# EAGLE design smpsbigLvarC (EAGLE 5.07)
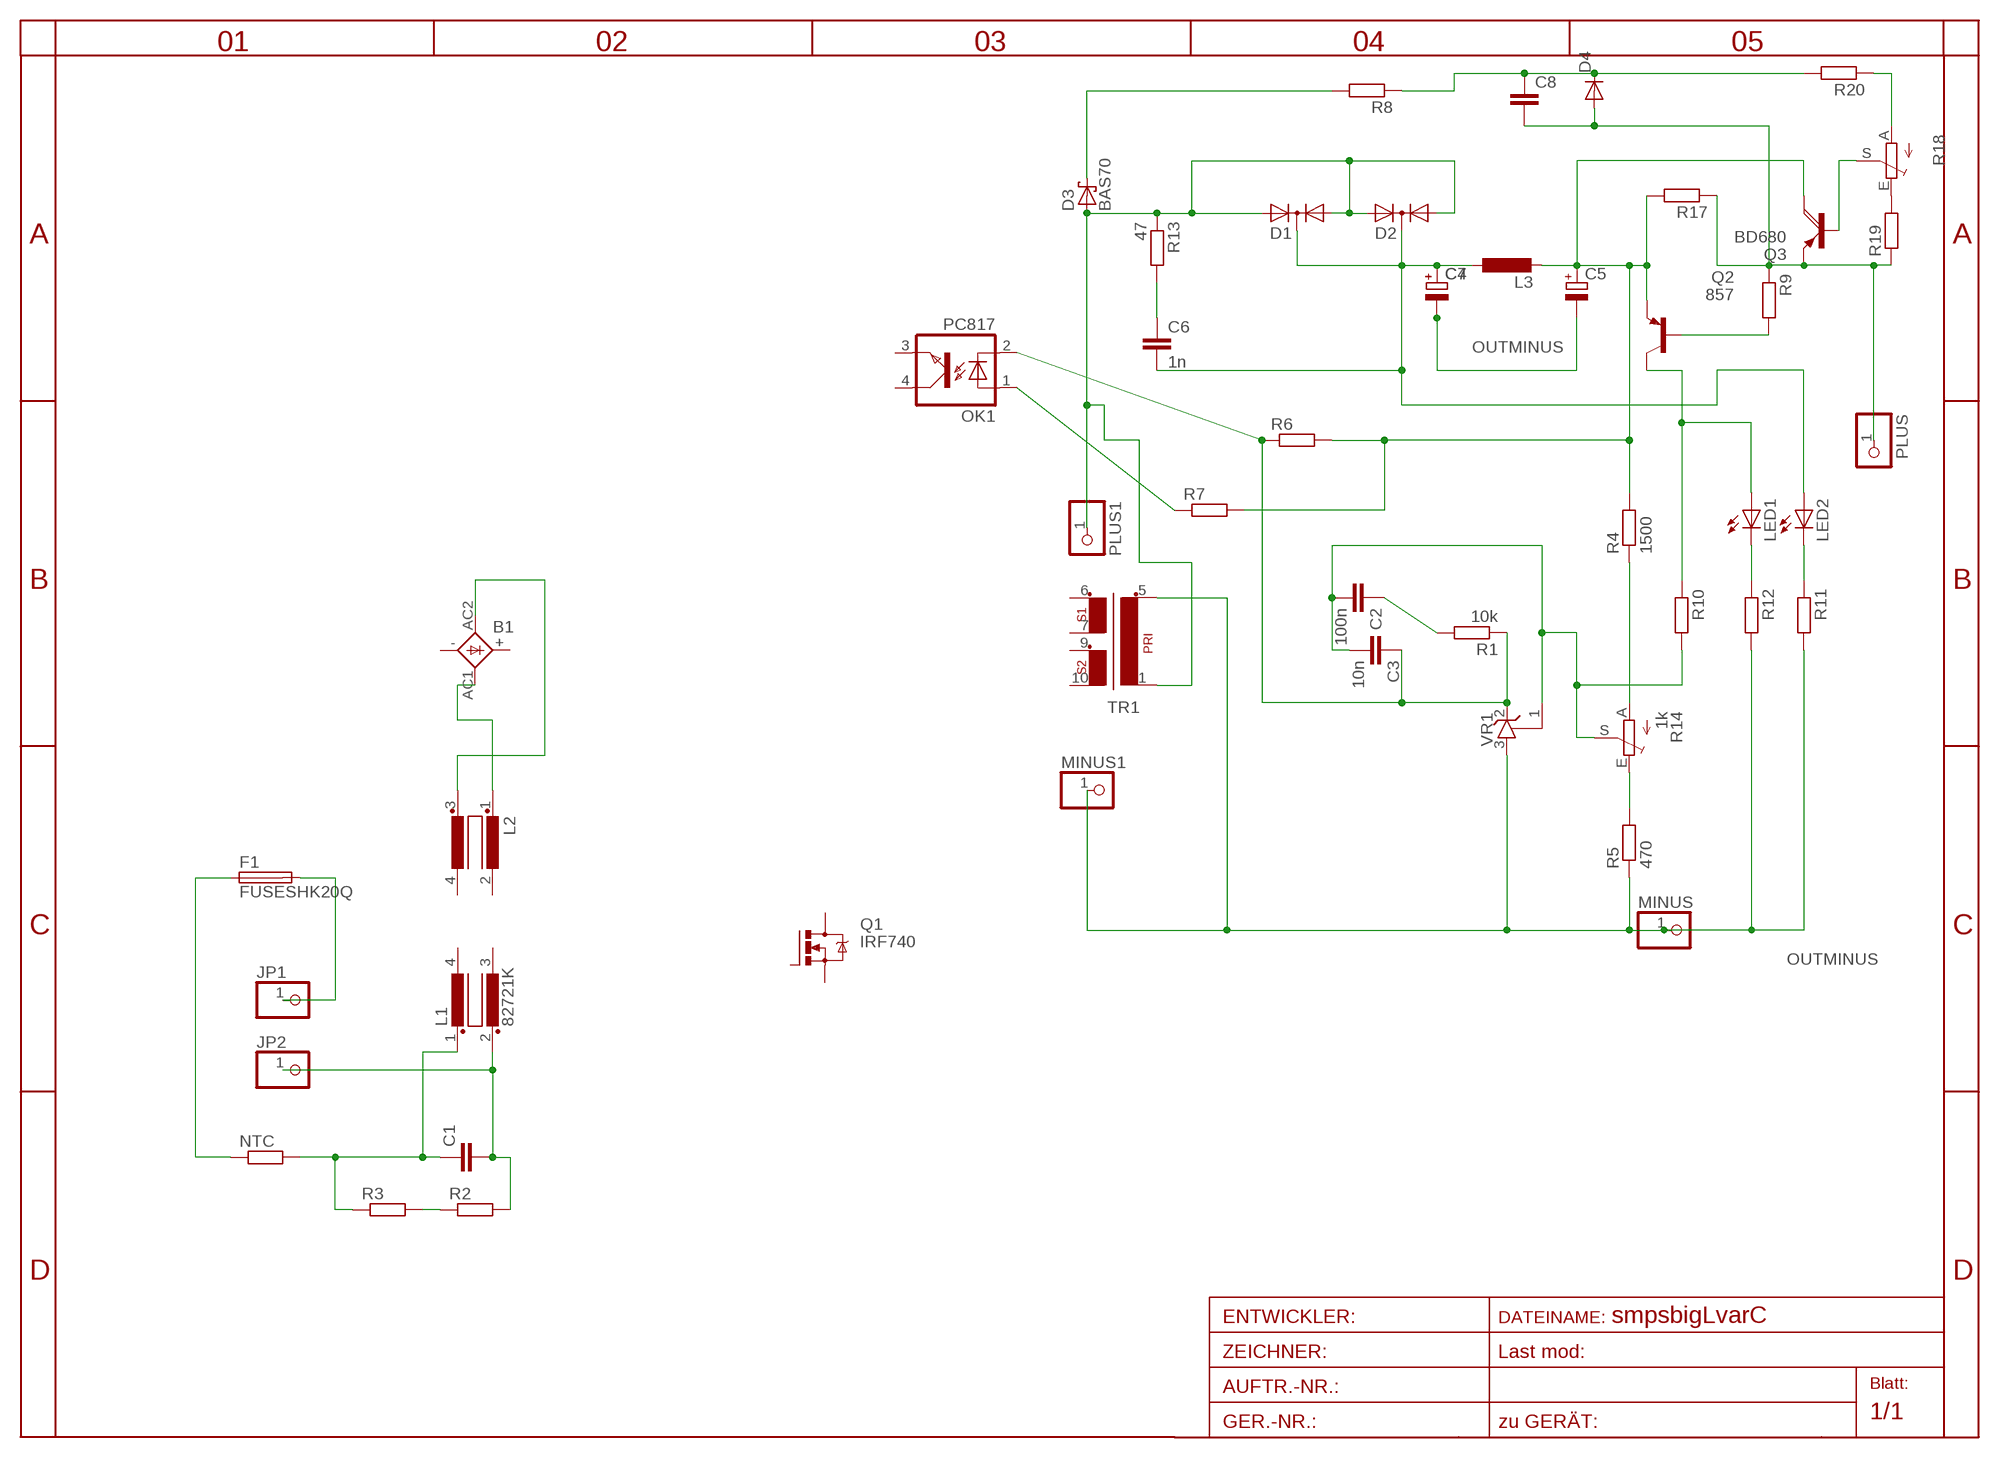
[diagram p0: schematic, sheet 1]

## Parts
B1  KBL  [KBL]
C1  C-EU150-084X183  [C150-084X183]
C2  100n  C-EUC0805  [C0805]
C3  10n  C-EUC0805  [C0805]
C4  CPOL-EUE5-8.5  [E5-8,5]
C5  CPOL-EUE5-8.5  [E5-8,5]
C6  1n  C-EUC1206  [C1206]
C7  CPOL-EUE3.5-8  [E3,5-8]
C8  C-EUC1206  [C1206]
D1  DIODE-2AC|CAIW220V  [IW220ABS]
D2  DIODE-2AC|CAIW220V  [IW220ABS]
D3  BAS70  [SOT23]
D4  DIODE-MINIMELF  [MINIMELF]
F1  FUSESHK20Q  [SHK20Q]
JP1  PINHD-1X12MM2  [1X2MM2]
JP2  PINHD-1X12MM2  [1X2MM2]
L1  82721K  [82721K]
L2  R1405VB1  [B1]
L3  L-EUOPEN6  [OPEN6_3]
LED1  LEDCHIPLED_1206  [CHIPLED_1206]
LED2  LEDCHIPLED_1206  [CHIPLED_1206]
MINUS  PINHD-1X12MM2  [1X2MM2]
MINUS1  PINHD-1X11X0.4  [1X01]
NTC  R-EU_0204/7  [0204/7]
OK1  PC817  [DIL04]
PLUS  PINHD-1X12MM2  [1X2MM2]
PLUS1  PINHD-1X11X0.4  [1X01]
Q1  IRF740  [TO220BV]
Q2  857  BC857ASMD  [SOT23-BEC]
Q3  BD680  [TO126AV]
R1  10k  R-EU_R0805  [R0805]
R2  R-EU_R1206  [R1206]
R3  R-EU_R1206  [R1206]
R4  1500  R-EU_R0805  [R0805]
R5  470  R-EU_R0805  [R0805]
R6  R-EU_R0805  [R0805]
R7  R-EU_R0805  [R0805]
R8  R-EU_R0805  [R0805]
R9  R-EU_R0805  [R0805]
R10  R-EU_R0805  [R0805]
R11  R-EU_R0805  [R0805]
R12  R-EU_R0805  [R0805]
R13  47  R-EU_R1206  [R1206]
R14  1k  TRIM_EU-S64W  [S64W]
R17  R-EU_R1206  [R1206]
R18  TRIM_EU-RAND160  [RANDL]
R19  R-EU_R0805  [R0805]
R20  R-EU_R0805  [R0805]
TR1  EE20-2  [EE30GREEN]
VR1  TL431CLPSOT23  [SOT23]

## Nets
A: R4.1 R14.A
C1: LED1.A Q2.C R10.1
CPLUS: C4.+ C6.2 C7.+ D1.C D2.C L3.1 LED2.A
E: R5.2 R14.E
N$1: C1.2 JP2.1 L1.2 R2.2
N$2: C1.1 L1.1 NTC.2 R3.1
N$3: F1.2A JP1.1
N$4: D3.3(C) R8.2
N$5: C8.1 D4.C R8.1 R20.2
N$6: R2.1 R3.2
N$7: B1.AC2(AC1) L2.3
N$8: B1.AC1(AC2) L2.1
N$9: F1.1A NTC.1
N$10: R18.E R19.2
N$11: C3.1 OK1.2(C) R1.1 R6.1 VR1.2(C)
N$12: OK1.1(A) R7.1
N$13: C2.1 R1.2
N$14: R18.A R20.1
N$15: Q3.B R18.S
N$16: Q2.B R9.2
N$21: LED1.C R12.1
N$23: LED2.C R11.1
N$27: C6.1 R13.2
OUTMINUS: C4.- C5.- C7.- MINUS1.1 MINUS.1 R5.1 R11.2 R12.2 TR1.5 VR1.3(A)
OUTPLUS: C8.2 D4.A PLUS.1 Q3.E R9.1 R17.1 R19.1
PLUS2: C5.+ L3.2 Q2.E Q3.C R4.2 R6.2 R7.2 R17.2
S: C2.2 C3.2 R10.2 R14.S VR1.1(R)
TOUT: D1.A1 D1.A2 D2.A1 D2.A2 D3.1(A) PLUS1.1 R13.1 TR1.1
Unconnected: B1.+ B1.- L1.3 L1.4 L2.2 L2.4 OK1.3(EMIT) OK1.4(COL) Q1.D Q1.G Q1.S TR1.6 TR1.7 TR1.9 TR1.10

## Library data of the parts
B1 = rectifier:KBL: DIOTEC RECTIFIER
C1-C3 C6 C8 = rcl:C-EU: CAPACITOR, European symbol
C4 C5 C7 = rcl:CPOL-EU: POLARIZED CAPACITOR, European symbol
D1 D2 = diode:DIODE-2AC|CA: Dual DIODE Anode-Cathode|Cathode-Anode
D3 = diode:BAS70: Silicon Schottky Diodes
D4 = diode:DIODE-: DIODE
F1 = fuse:FUSE: Fuse
JP1 JP2 MINUS MINUS1 PLUS PLUS1 = pinhead:PINHD-1X1: PIN HEADER
L1 = inductors:82721K: FILTER
L2 = inductor-nkl:R1405V: Übertrager (verlustarm) bis typ. 400kHz Power transformer (low loss) up to typ. 400kHz
L3 = rcl:L-EU: INDUCTOR, European symbol
LED1 LED2 = led:LED: LED
NTC R1-R13 R17 R19 R20 = rcl:R-EU_: RESISTOR, European symbol
OK1 = optocoupler:PC817: SHARP OPTO COUPLER
Q1 = transistor-power:IRF740: N-CHANNEL MOS FET
Q2 = transistor-pnp:BC857*: PNP Transistror
Q3 = transistor-power:BD680: PNP DARLINGTON TRANSISTOR
R14 R18 = pot:TRIM_EU-: POTENTIOMETER
TR1 = trafo:EE20-2: TRANSFORMER 1 primary winding, 2 secondary windings ERA
VR1 = v-reg:TL431CLP: VOLTAGE REGULATOR

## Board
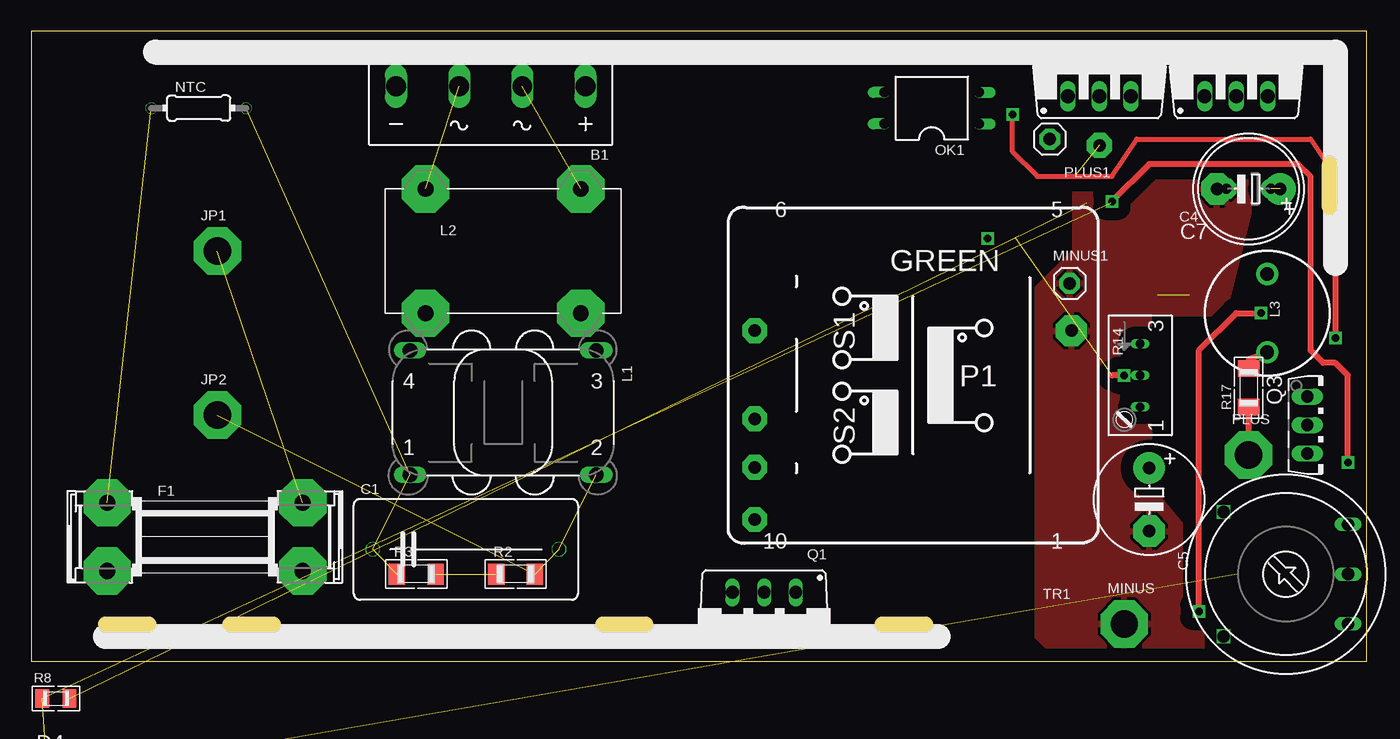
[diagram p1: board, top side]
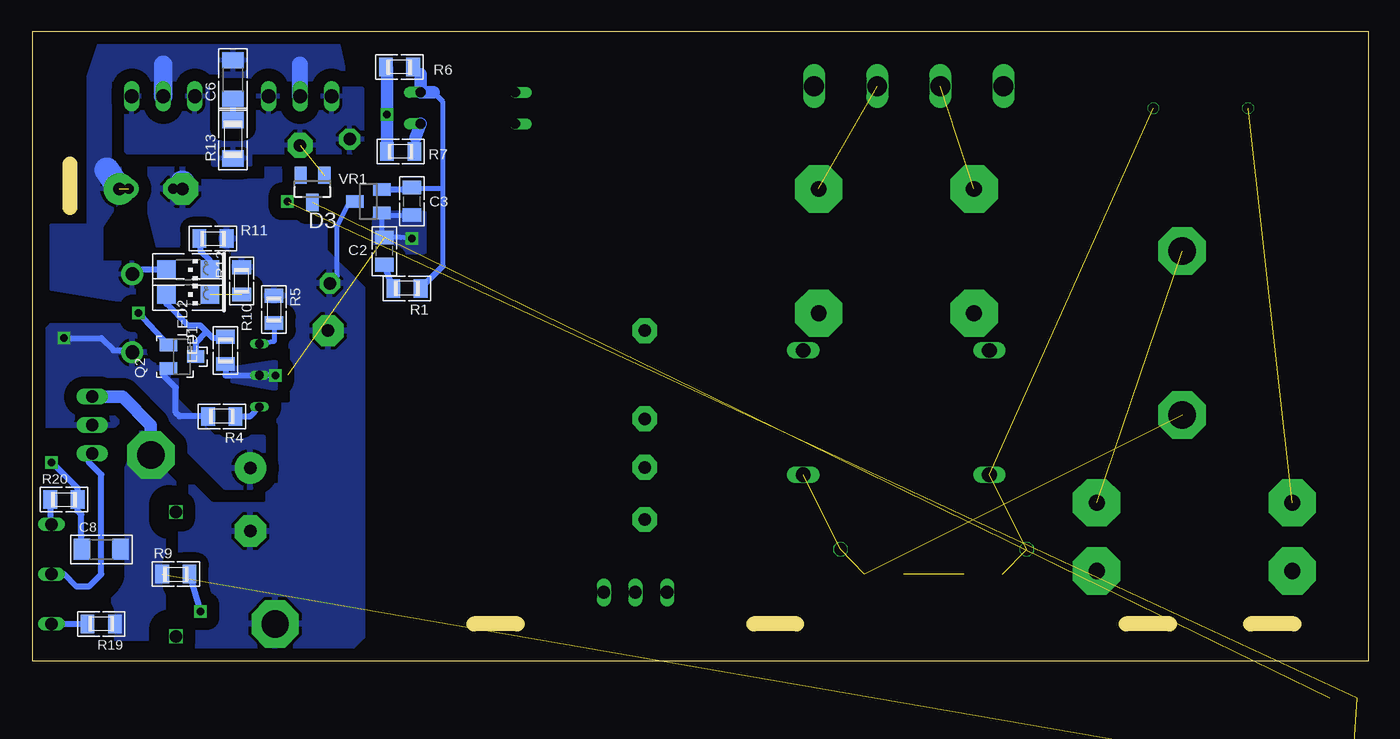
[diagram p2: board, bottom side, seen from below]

Size 107.5 x 50.7 mm. Coordinates in mm from the lower left corner, seen from the top.
Outline: 0,0 107.5,0 107.5,50.7 0,50.7 0,0
Copper layers (1*16): Top 0.035mm / dielectric 1.5mm / Bottom 0.035mm
Design rules "default": minimum track width 10mil, minimum drill 20mil, track to track 8mil, track to pad 8mil, pad to pad 8mil, via to via 8mil, smd to smd 8mil, copper to edge 40mil, drill to drill 8mil, minimum pad ring 1mil, minimum via ring 8mil, stop-mask expansion 4mil, vias tented up to drill 0mil, thermal gap 10mil
Milling: 5 lines

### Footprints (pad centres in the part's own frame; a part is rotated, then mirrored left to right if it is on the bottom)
KBL = drill 1.6 long: + -7.62,-1.27; - 7.62,-1.27; AC1 2.54,-1.27; AC2 -2.54,-1.27
C150-084X183 = drill 1.016 octagon: 1 -7.493,0; 2 7.493,0
C0805 = smd 1.1 x 1.5: 1 -1.1,0; 2 1.1,0
E5-8,5 = drill 1 pad 2.54 round: + -2.54,0 | drill 1 pad 2.54 octagon: - 2.54,0
C1206 = smd 1.3 x 1.7: 1 -1.55,0; 2 1.55,0
E3,5-8 = drill 0.813 pad 1.6 round: + -1.778,0 | drill 0.813 pad 1.6 octagon: - 1.778,0
IW220ABS = drill 1.118 long: A1 -2.54,-2.54; A2 2.54,-2.54; C 0,-2.54
SOT23 = smd 1 x 1.4: 1 -0.95,-1.1; 2 0.95,-1.1; 3 0,1.1
MINIMELF = smd 1.4 x 1.8: A 1.7,0; C -1.7,0
SHK20Q = drill 1.3 pad 3.81 octagon: 1A -7.874,2.75; 1B -7.874,-2.75; 2A 7.874,2.75; 2B 7.874,-2.75
1X2MM2 = drill 2.2 pad 3.81 octagon: 1 0,0
82721K = drill 1.194 long: 1 7.493,5.004; 2 -7.493,5.004; 3 -7.493,-5.004; 4 7.493,-5.004
B1 = drill 1.27 pad 3.81 octagon: 1 -6.25,5; 2 -6.25,-5; 3 6.25,5; 4 6.25,-5
OPEN6_3 = drill 1.1 pad 1.778 round: 1 -3.15,0; 2 3.15,0
CHIPLED_1206 = smd 1.5 x 1.5: A 0,-1.75; C 0,1.75
1X01 = drill 1 pad 1.676 octagon: 1 0,0
0204/7 = drill 0.813 octagon: 1 -3.81,0; 2 3.81,0
DIL04 = drill 0.813 offset: 1 -1.27,-3.81; 2 1.27,-3.81; 3 1.27,3.81; 4 -1.27,3.81
TO220BV = drill 1.016 long: D 0,-2.54; G -2.54,-2.54; S 2.54,-2.54
SOT23-BEC = smd 1 x 1.4: B -0.95,-1.1; C 0,1.1; E 0.95,-1.1
TO126AV = drill 1 pad 1.27 long: B 2.286,-1.27; C 0,-1.27; E -2.286,-1.27
R0805 = smd 1.1 x 1.5: 1 -1.1,0; 2 1.1,0
R1206 = smd 1.3 x 1.7: 1 -1.55,0; 2 1.55,0
S64W = drill 0.7 long: A 2.54,1.27; E -2.54,1.27; S 0,1.27
RANDL = drill 1 long: A -4,5; E 4,5; S 0,5 | drill 1 square: P$1 -5,-5; P$2 5,-5
EE30GREEN = drill 1 pad 2 octagon: 1 15,18.5; 6 -12.75,3.6; 7 -12.75,-3.5; 9 -12.75,-7.4; 10 -12.75,-11.6 | drill 1 pad 2.5 octagon: 5 12.75,3.6

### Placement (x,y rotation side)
B1  37,45 180 top
C1  35,9 0 top
C2  79.2,33 90 bottom
C3  77,37 270 bottom
C4  98,38 180 top
C5  90,13 270 top
C6  91.4,46.8 90 bottom
C7  98,38 180 top
C8  102,9 0 bottom
D1  97,48 0 top
D2  86,48 0 top
D3  85,38 180 bottom
D4  not placed on the board
F1  14,10 0 top
JP1  15,33 0 top
JP2  15,19.8 0 top
L1  38,20 180 top
L2  38,33 0 top
L3  99.5,28 270 top
LED1  95,29.5 270 bottom
LED2  95,31.5 270 bottom
MINUS  88,3 0 top
MINUS1  83.6,30.4 0 top
NTC  13.5,44.5 0 top
OK1  72.5,44.5 90 top
PLUS  98,16.6 0 top
PLUS1  82,42 0 top
Q1  59,3 180 top
Q2  95.5,24.5 270 bottom
Q3  104,19 270 top
R1  77.4,30 180 bottom
R2  39,7 0 top
R3  31,7 0 top
R4  92.3,19.7 180 bottom
R5  88.1,28.3 270 bottom
R6  78,47.8 180 bottom
R7  77.9,41 180 bottom
R8  2,-3 0 top
R9  96,7 0 bottom
R10  92,25 270 bottom
R11  93,34 0 bottom
R12  90.7,30.6 90 bottom
R13  91.4,42 90 bottom
R14  88,23 270 top
R17  98,22 90 top
R18  101,7 270 top
R19  102,3 180 bottom
R20  105,13 0 bottom
TR1  71,23 0 top
VR1  80.5,37 90 bottom

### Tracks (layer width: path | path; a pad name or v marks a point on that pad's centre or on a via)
A
  Bottom 0.5: R4.1 90.03,19.7 R14.A
C1
  Bottom 0.5: LED1.A 96.75,28.75 95,27 94,27 93.5,26.5 | 93.5,26.5 93,26 92.1,26 R10.1 | Q2.C 94.4,25.6 93.5,26.5
CPLUS  (1 unrouted)
  Bottom 0.5: LED2.A 99.5,31.5 100,31 99.65,31 L3.1
  Bottom 1.27: D2.C 86,48
  Bottom 1.5: D1.C 97,48
  Bottom 2: C4.+ 101.54,39.54
  pour Bottom (isolate 1, rank 3): 83,50 102,50 103,47 103,35 106,35 106,30 99.4,28.9 99.4,32 102,32 102,35 100,38 101.1,45.8 82.1,45.8
E
  Bottom 0.406: R5.2 88.1,25.71 R14.E
N$1  (3 unrouted)
N$2  (3 unrouted)
N$3  (1 unrouted)
N$4  (1 unrouted)
N$5  (via drill 0.6)  (2 unrouted)
  Top 0.5: v87,37 90,40 102,40 103,39 103,25 104,24 105,24 106,23 v106,16
  Bottom 0.5: v87,37 86.9,36.9 | v106,16 103.9,13.9 R20.2 103.9,12.1 103.6,11.8 103.6,10.05 C8.1
N$6  (1 unrouted)
N$7  (1 unrouted)
N$8  (1 unrouted)
N$9  (1 unrouted)
N$10
  Bottom 0.5: R18.E R19.2 103,3
N$11
  Bottom 0.406: 77.15,37.95 C3.1 76.9,38 74.5,38 | 74.5,31.8 74.5,38 | 76.31,47.21 R6.1 | 75.23,45.77 74.5,45 74.5,38
  Bottom 0.5: 77.15,37.95 VR1.2 | R1.1 74.5,31.8
  Bottom 1: 76.31,47.21 OK1.2 75.23,45.77
N$12
  Bottom 0.5: R7.1 76.7,42.14
  Bottom 1: 76.7,42.14 OK1.1
N$13
  Bottom 0.5: R1.2 C2.1
N$14
  Bottom 0.5: R20.1 106.1,11.1 R18.A
N$15
  Bottom 0.5: R18.S 105,7 104,6 103,6 102,7 102,15 103,16 103,16.44 Q3.B
N$16  (via drill 0.6)
  Top 0.5: v99,28 97,28 94,25 v94,4
  Bottom 0.5: Q2.B 98.6,27.6 v99,28 | v94,4 R9.2
N$21  (1 unrouted)
N$23
  Bottom 0.5: LED2.C 93.25,32.25 94,33 94,33.9 R11.1
N$27
  Bottom 0.5: R13.2 C6.1
OUTMINUS
  Bottom 0.406: VR1.3 82,37 83,35 83,31 MINUS1.1
  Bottom 2: C4.- 95.46,38.46
  pour Bottom (isolate 1, rank 5): 98,40 84,40 84,33 81,30 81,2 82,1 106,1 107,2 107,6 106,7 101,7 101,14 90,14 90,28 96,28 98,36
  pour Top (isolate 1, rank 5): 98,40 84,40 84,33 81,30 81,2 82,1 95,1 95,8 90,14 90,28 96,28 98,36
OUTPLUS  (1 unrouted)
  Top 0.5: PLUS.1 R17.1
  Bottom 1.016: Q3.E 100.29,21.29 98,19 PLUS.1
  pour Bottom (isolate 1.6, rank 4, no thermals): 95,21 100,21 101,20 101,2 100,1 99,1 97,3 97,12 95,14
PLUS2  (via drill 0.6)
  Top 0.406: 105,39 103,42 89,42 87,39 81,39 R7.2 v79,44
  Top 0.5: Q3.C 103,19 | R17.2 98,24.25 L3.2 | 105,39 v105,26
  Bottom 0.406: 79,47.7 R6.2 | v79,44 79,48
  Bottom 0.5: v105,26 102,26 101,25 99.65,25 L3.2 | R4.2 95.7,19.7 96,20 96,22 97,23 97,23.15 Q2.E
  Bottom 1: R7.2 v79,44 79,47.7
  pour Bottom (isolate 1, rank 3): 89,18 89,14 92,14 98,20 100,20 101,19 107,19 107,26 106,27 100,27 96,23 96,21 93,18
S  (via drill 0.6)  (1 unrouted)
  Top 0.5: v88,23 87,23
  Bottom 0.406: C3.2 79.25,35.9 VR1.1 79.4,34.3 C2.2 77.9,34.1 v77,34
  Bottom 0.5: v88,23 R14.S 92,23 R10.2
  pour Bottom (isolate 1, no thermals): 88,24 91.4,23.5 91.4,22.6 88,22
  pour Bottom (isolate 1, rank 3, no thermals): 76,36 80,36 80,33 76,33
TOUT  (1 unrouted)
  pour Bottom (isolate 1, rank 2): 81,46 100,46 100,41 93,41 93,40 90,40 90,41 81,41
